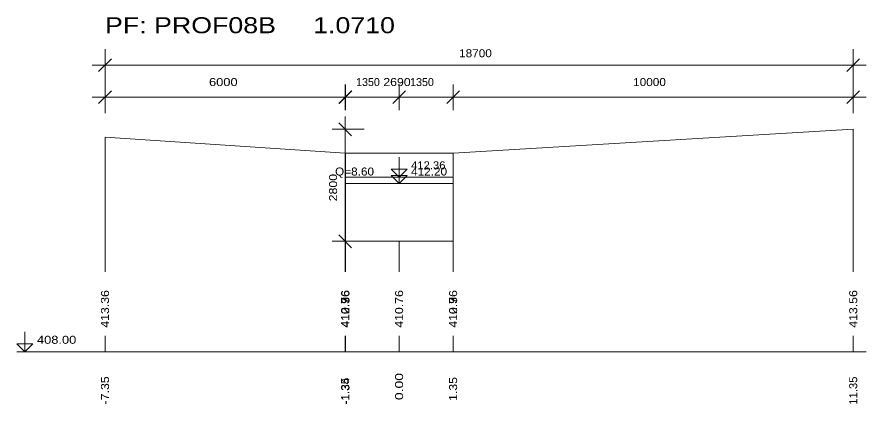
# Model space of a CAD drawing. Extents: x 7 to 442, y -393 to 441.
# Drawn here: x 292.08 to 313.31, y -85.11 to -75.43 of the extents above; entities that cross this region are included whole.
import ezdxf

# ---------------------------------------------------------------- set-up
doc = ezdxf.new("R2010")
doc.units = 0
doc.header["$LTSCALE"] = 0.08
doc.layers.add('7', color=7, linetype='Continuous', lineweight=13)

msp = doc.modelspace()

# ---------------------------------------------------------------- linework, layer by layer
at = {"layer": '7'}
for p, q in [((294.285, -77.84), (294.285, -76.24)), ((312.985, -77.84), (312.985, -76.24)), ((294.125, -76.8), (294.445, -76.48)), ((312.825, -76.8), (313.145, -76.48)), ((293.965, -76.64), (313.305, -76.64)), ((294.285, -77.76), (294.285, -77.12)), ((300.285, -77.76), (300.285, -77.12)), ((300.285, -77.76), (300.285, -77.12)), ((300.295, -77.76), (300.295, -77.12)), ((300.295, -77.76), (300.295, -77.12)), ((301.635, -77.76), (301.635, -77.12)), ((302.985, -77.76), (302.985, -77.12)), ((302.985, -77.76), (302.985, -77.12)), ((302.985, -77.76), (302.985, -77.12)), ((312.985, -77.76), (312.985, -77.12)), ((293.965, -77.44), (313.305, -77.44)), ((294.125, -77.6), (294.445, -77.28)), ((300.125, -77.6), (300.445, -77.28)), ((300.125, -77.6), (300.445, -77.28)), ((300.135, -77.6), (300.455, -77.28)), ((300.135, -77.6), (300.455, -77.28)), ((301.475, -77.6), (301.795, -77.28)), ((302.825, -77.6), (303.145, -77.28)), ((302.825, -77.6), (303.145, -77.28)), ((302.825, -77.6), (303.145, -77.28)), ((312.825, -77.6), (313.145, -77.28)), ((300.445, -78.4), (300.125, -78.08)), ((300.285, -81.2), (300.285, -77.92)), ((299.965, -78.24), (300.765, -78.24)), ((312.985, -81.8), (312.985, -78.24)), ((294.285, -81.8), (294.285, -78.44)), ((300.285, -81.8), (300.285, -78.84)), ((300.295, -81.8), (300.295, -78.84)), ((302.985, -81.8), (302.985, -78.84)), ((300.285, -79.44), (300.295, -79.44)), ((300.295, -81.8), (300.295, -79.44)), ((302.985, -81.8), (302.985, -79.44)), ((300.285, -79.596), (302.985, -79.596)), ((299.965, -81.04), (300.765, -81.04)), ((300.445, -81.2), (300.125, -80.88)), ((300.285, -81.8), (300.285, -81.04)), ((301.635, -81.8), (301.635, -81.04)), ((302.985, -81.8), (302.985, -81.04)), ((294.285, -83.8), (294.285, -83.4)), ((300.285, -83.8), (300.285, -83.4)), ((300.285, -83.8), (300.285, -83.4)), ((300.295, -83.8), (300.295, -83.4)), ((300.295, -83.8), (300.295, -83.4)), ((301.635, -83.8), (301.635, -83.4)), ((302.985, -83.8), (302.985, -83.4)), ((302.985, -83.8), (302.985, -83.4)), ((302.985, -83.8), (302.985, -83.4)), ((312.985, -83.8), (312.985, -83.4)), ((292.085, -83.8), (313.305, -83.8))]:
    msp.add_line(p, q, dxfattribs=at)
for points in [[(294.285, -78.44), (300.285, -78.84), (300.285, -81.04), (301.635, -81.04), (302.985, -81.04), (302.985, -79.44), (300.295, -79.44), (300.295, -78.84), (302.985, -78.84), (312.985, -78.24)], [(301.635, -78.94), (301.635, -79.44), (301.435, -79.24), (301.835, -79.24), (301.635, -79.44)], [(301.635, -79.096), (301.635, -79.596), (301.435, -79.396), (301.835, -79.396), (301.635, -79.596)], [(292.285, -83.3), (292.285, -83.8), (292.085, -83.6), (292.485, -83.6), (292.285, -83.8)]]:
    msp.add_lwpolyline(points, dxfattribs=at)

# ---------------------------------------------------------------- texts
for s, height, width, p in [('PF: PROF08B     1.0710', 0.4, 1.25, (294.285, -75.84)), ('18700', 0.2, 1.1, (303.135, -76.44)), ('6000', 0.2, 1.2, (296.885, -77.16)), ('2690', 0.2, 1.15, (301.24, -77.16)), ('10000', 0.2, 1.1, (307.485, -77.16)), ('412.36', 0.2, 1.05, (301.935, -79.24)), ('Q=8.60', 0.2, 1.1, (300.035, -79.396)), ('412.20', 0.2, 1.1, (301.935, -79.396)), ('408.00', 0.2, 1.2, (292.585, -83.6))]:
    msp.add_text(s, height=height, dxfattribs=dict(at, width=width)).set_placement(p)
for p in [(300.56, -77.16), (301.91, -77.16)]:
    msp.add_text('1350', height=0.2, dxfattribs=at).set_placement(p)
for s, width, p in [('2800', 1.15, (300.085, -80.04)), ('413.36 ', 1.15, (294.385, -83.2)), ('412.96 ', 1.15, (300.385, -83.2)), ('410.76 ', 1.15, (300.385, -83.2)), ('412.36 ', 1.15, (300.395, -83.2)), ('412.96 ', 1.15, (300.395, -83.2)), ('410.76 ', 1.15, (301.735, -83.2)), ('410.76 ', 1.15, (303.085, -83.2)), ('412.36 ', 1.15, (303.085, -83.2)), ('412.96 ', 1.15, (303.085, -83.2)), ('413.56 ', 1.15, (313.085, -83.2)), (' -7.35 ', 1.15, (294.385, -85.2)), ('  0.00 ', 1.3, (301.735, -85.2)), ('  1.35 ', 1.15, (303.085, -85.2)), ('  1.35 ', 1.15, (303.085, -85.2)), ('  1.35 ', 1.15, (303.085, -85.2)), (' 11.35 ', 1.05, (313.085, -85.2)), (' -1.35 ', 1.1, (300.385, -85.2)), (' -1.35 ', 1.1, (300.385, -85.2)), (' -1.34 ', 1.1, (300.395, -85.2)), (' -1.34 ', 1.1, (300.395, -85.2))]:
    msp.add_text(s, height=0.2, rotation=90, dxfattribs=dict(at, width=width)).set_placement(p)

doc.saveas('drawing.dxf')
